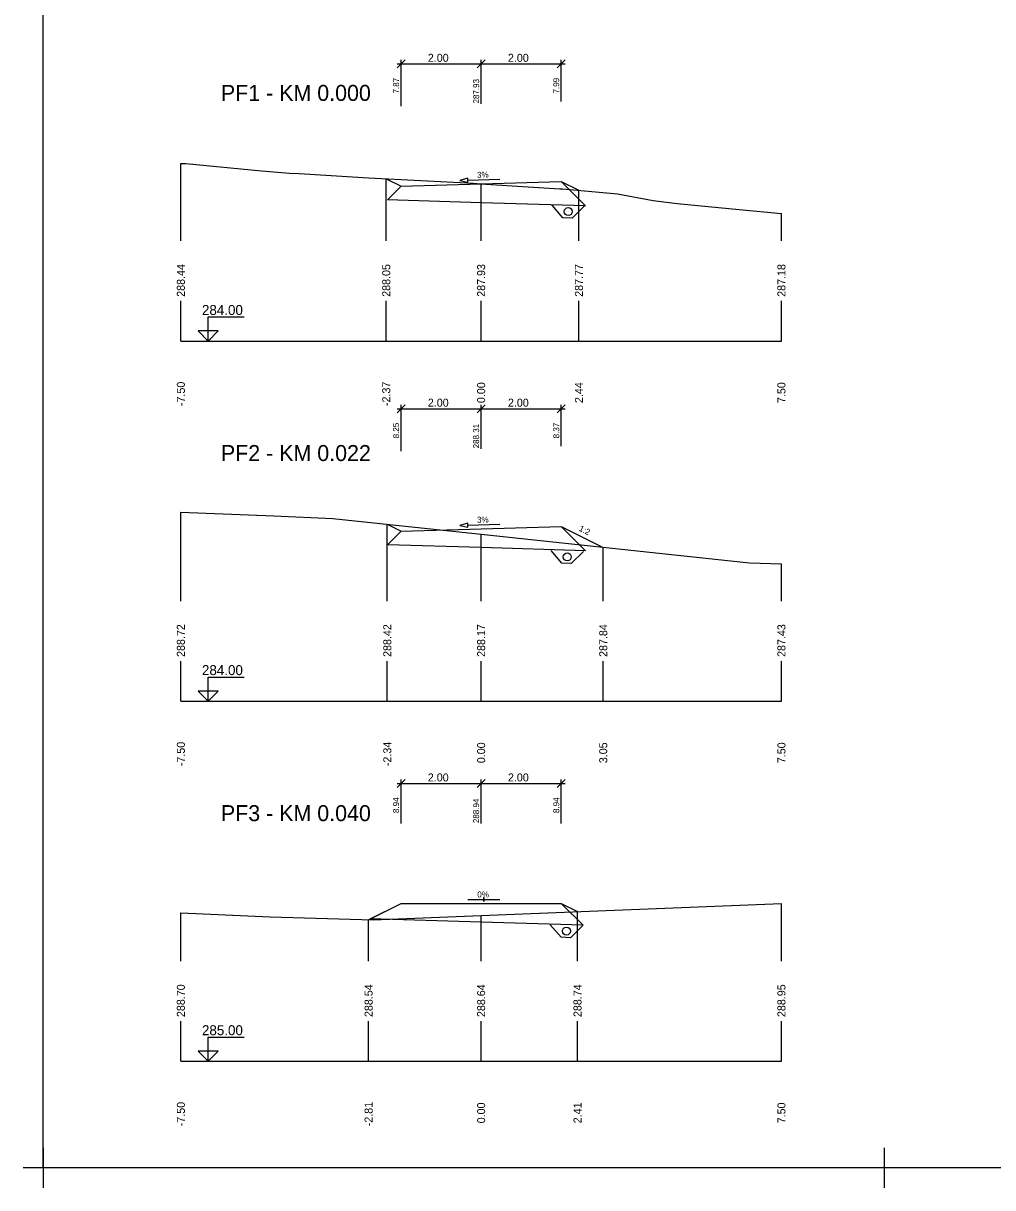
# Model space of a CAD drawing. Extents: x -9 to 2311, y -2 to 597.
# Drawn here: x -9.3 to 232.8, y -1.6 to 289.4 of the extents above; entities that cross this region are included whole.
import ezdxf

# ---------------------------------------------------------------- set-up
doc = ezdxf.new("R2010")
doc.units = 0
for name, color, linetype in [('KOTA', 7, 'Continuous'), ('KOTA_DELKY', 7, 'Continuous'), ('KOTA_DELKY_CONT', 7, 'Continuous'), ('NS_TELESO_VOZOVKY', 7, 'Continuous'), ('NS_V_PF', 7, 'Continuous'), ('REZY_PF_PUVODNI', 7, 'Continuous'), ('SESTAVY_REZU_PF', 7, 'Continuous'), ('SKLON', 7, 'Continuous'), ('SVK', 7, 'Continuous')]:
    doc.layers.add(name, color=color, linetype=linetype)

msp = doc.modelspace()

# ---------------------------------------------------------------- linework, layer by layer
for p, q in [((-4.35, 8.39), (-4.35, -1.61)), ((-4.35, 8.39), (-4.35, -1.61)), ((-4.35, 8.39), (-4.35, -1.61)), ((-4.35, 8.39), (-4.35, -1.61)), ((205.65, 8.39), (205.65, -1.61)), ((205.65, 8.39), (205.65, -1.61)), ((205.65, 8.39), (205.65, -1.61)), ((205.65, 8.39), (205.65, -1.61)), ((0.65, 3.39), (-9.35, 3.39)), ((0.65, 3.39), (-9.35, 3.39)), ((0.65, 3.39), (-9.35, 3.39)), ((0.65, 3.39), (-9.35, 3.39)), ((210.65, 3.39), (200.65, 3.39)), ((210.65, 3.39), (200.65, 3.39)), ((210.65, 3.39), (200.65, 3.39)), ((210.65, 3.39), (200.65, 3.39))]:
    msp.add_line(p, q)
msp.add_lwpolyline([(-4.35, 597.39), (2305.65, 597.39), (2305.65, 3.39), (-4.35, 3.39)], close=True)
for points in [[(130.8, 243.76), (127.75, 240.72), (125.4, 240.82), (122.7, 243.96)], [(130.58, 157.43), (127.52, 154.39), (125.18, 154.49), (122.47, 157.63)], [(130.38, 63.91), (127.33, 60.87), (124.98, 60.97), (122.27, 64.11)]]:
    msp.add_lwpolyline(points)
for centre in [(126.74, 242.36), (126.52, 156.03), (126.32, 62.51)]:
    msp.add_circle(centre, 1)
at = {"layer": 'KOTA'}
for points in [[(36.85, 212.5), (34.35, 212.5), (36.85, 210), (36.85, 216), (45.85, 216)], [(36.85, 210), (39.35, 212.5), (36.85, 212.5)], [(36.85, 122.5), (34.35, 122.5), (36.85, 120), (36.85, 126), (45.85, 126)], [(36.85, 120), (39.35, 122.5), (36.85, 122.5)], [(36.85, 32.5), (34.35, 32.5), (36.85, 30), (36.85, 36), (45.85, 36)], [(36.85, 30), (39.35, 32.5), (36.85, 32.5)]]:
    msp.add_lwpolyline(points, dxfattribs=at)
at = {"layer": 'KOTA_DELKY'}
for points in [[(84, 278.27), (86, 280.27)], [(85, 268.67), (85, 280.27)], [(104, 278.27), (106, 280.27)], [(104, 278.27), (106, 280.27)], [(105, 269.27), (105, 280.27)], [(105, 269.27), (105, 280.27)], [(124, 278.27), (126, 280.27)], [(125, 269.87), (125, 280.27)], [(84, 279.27), (106, 279.27)], [(104, 279.27), (126, 279.27)], [(84, 192.08), (86, 194.08)], [(84, 193.08), (106, 193.08)], [(85, 182.48), (85, 194.08)], [(104, 192.08), (106, 194.08)], [(104, 192.08), (106, 194.08)], [(104, 193.08), (126, 193.08)], [(105, 183.08), (105, 194.08)], [(105, 183.08), (105, 194.08)], [(124, 192.08), (126, 194.08)], [(125, 183.68), (125, 194.08)], [(84, 98.43), (86, 100.43)], [(84, 99.43), (106, 99.43)], [(85, 89.43), (85, 100.43)], [(104, 98.43), (106, 100.43)], [(104, 98.43), (106, 100.43)], [(104, 99.43), (126, 99.43)], [(105, 89.43), (105, 100.43)], [(105, 89.43), (105, 100.43)], [(124, 98.43), (126, 100.43)], [(125, 89.43), (125, 100.43)]]:
    msp.add_lwpolyline(points, dxfattribs=at)
at = {"layer": 'NS_TELESO_VOZOVKY'}
for points in [[(105, 249.27), (125, 249.87), (125, 249.87), (131.08, 243.79), (105, 244.57), (81.6, 245.28), (85, 248.67), (85, 248.67), (105, 249.27)], [(105, 163.08), (125, 163.68), (125, 163.68), (131.08, 157.6), (105, 158.38), (81.6, 159.08), (85, 162.48), (85, 162.48), (105, 163.08)], [(105, 69.43), (125, 69.43), (125, 69.43), (130.46, 63.97), (105, 64.73), (77.26, 65.57), (85, 69.43), (85, 69.43), (105, 69.43)]]:
    msp.add_lwpolyline(points, dxfattribs=at)
at = {"layer": 'NS_V_PF'}
for points in [[(81.3, 250.53), (85, 248.67), (85, 248.67), (105, 249.27), (125, 249.87), (125, 249.87), (129.43, 247.66)], [(81.56, 164.2), (85, 162.48), (85, 162.48), (105, 163.08), (125, 163.68), (125, 163.68), (135.5, 158.43)], [(76.89, 65.38), (85, 69.43), (85, 69.43), (105, 69.43), (125, 69.43), (125, 69.43), (129.07, 67.4)]]:
    msp.add_lwpolyline(points, dxfattribs=at)
at = {"layer": 'REZY_PF_PUVODNI'}
for points in [[(30, 254.39), (31.22, 254.33), (50.11, 252.52), (57.15, 251.92), (59.54, 251.82), (76.9, 250.75), (103, 249.42), (105, 249.27), (106.17, 249.19), (124.67, 248.02), (125.35, 248.04), (139.08, 246.77), (147.98, 245.13), (153.99, 244.34), (169.47, 242.89), (180, 241.85)], [(30, 167.2), (53.19, 166.28), (67.96, 165.65), (105, 161.69), (105, 161.69), (172.03, 154.52), (180, 154.35)], [(30, 67.05), (52.28, 66.11), (78, 65.34), (105, 66.43), (105, 66.43), (180, 69.45)]]:
    msp.add_lwpolyline(points, dxfattribs=at)
at = {"layer": 'SESTAVY_REZU_PF'}
for points in [[(30, 210), (180, 210)], [(30, 120), (180, 120)], [(30, 30), (180, 30)]]:
    msp.add_lwpolyline(points, dxfattribs=at)
at = {"layer": 'SKLON'}
for points in [[(101.64, 250.67), (99.66, 250.11), (101.67, 249.68), (101.64, 250.67)], [(101.65, 250.17), (109.65, 250.41)], [(101.64, 164.48), (99.66, 163.92), (101.67, 163.48), (101.64, 164.48)], [(101.65, 163.98), (109.65, 164.22)], [(101.68, 70.43), (109.68, 70.43)], [(105.68, 70.93), (105.68, 70.43), (105.68, 69.93), (105.68, 70.93)]]:
    msp.add_lwpolyline(points, dxfattribs=at)
at = {"layer": 'SVK'}
for points in [[(30, 235), (30, 254.39)], [(81.3, 235), (81.3, 250.53)], [(105, 235), (105, 249.27)], [(129.43, 235), (129.43, 247.66)], [(180, 235), (180, 241.85)], [(30, 210), (30, 220)], [(81.3, 210), (81.3, 220)], [(105, 210), (105, 220)], [(129.43, 210), (129.43, 220)], [(180, 210), (180, 220)], [(30, 145), (30, 167.2)], [(81.56, 145), (81.56, 164.2)], [(105, 145), (105, 161.69)], [(135.5, 145), (135.5, 158.43)], [(180, 145), (180, 154.35)], [(30, 120), (30, 130)], [(81.56, 120), (81.56, 130)], [(105, 120), (105, 130)], [(135.5, 120), (135.5, 130)], [(180, 120), (180, 130)], [(30, 55), (30, 67.05)], [(129.07, 55), (129.07, 67.4)], [(180, 55), (180, 69.45)], [(76.89, 55), (76.89, 65.38)], [(105, 55), (105, 66.43)], [(30, 30), (30, 40)], [(76.89, 30), (76.89, 40)], [(105, 30), (105, 40)], [(129.07, 30), (129.07, 40)], [(180, 30), (180, 40)]]:
    msp.add_lwpolyline(points, dxfattribs=at)

# ---------------------------------------------------------------- texts
at = {"layer": 'KOTA'}
for s, p in [('284.00', (35.27, 216.5)), ('284.00', (35.27, 126.5)), ('285.00', (35.27, 36.5))]:
    msp.add_text(s, height=2.5, dxfattribs=at).set_placement(p)
at = {"layer": 'KOTA_DELKY'}
for p in [(91.69, 279.77), (111.69, 279.77), (91.69, 193.58), (111.69, 193.58), (91.69, 99.93), (111.69, 99.93)]:
    msp.add_text('2.00', height=2, dxfattribs=at).set_placement(p)
at = {"layer": 'KOTA_DELKY_CONT'}
for s, p in [('7.87', (84.5, 271.86)), ('287.93', (104.5, 269.35)), ('7.99', (124.5, 271.86)), ('8.25', (84.5, 185.67)), ('288.31', (104.5, 183.16)), ('8.37', (124.5, 185.67)), ('8.94', (84.5, 92.02)), ('288.94', (104.5, 89.51)), ('8.94', (124.5, 92.02))]:
    msp.add_text(s, height=1.5, rotation=90, dxfattribs=at).set_placement(p)
at = {"layer": 'SESTAVY_REZU_PF'}
for s, p in [('PF1 - KM 0.000', (40, 270)), ('PF2 - KM 0.022', (40, 180)), ('PF3 - KM 0.040', (40, 90))]:
    msp.add_text(s, height=4, dxfattribs=at).set_placement(p)
at = {"layer": 'SKLON'}
for s, rotation, p in [('3%', 1.7184, (104, 250.75)), ('3%', 1.7184, (104, 164.55)), ('1:2', 333.4349, (129.29, 162.65))]:
    msp.add_text(s, height=1.5, rotation=rotation, dxfattribs=at).set_placement(p)
msp.add_text('0%', height=1.5, dxfattribs=at).set_placement((104.04, 70.93))
at = {"layer": 'SVK'}
for s, p in [(' 288.44', (31, 220.3)), (' 288.05', (82.3, 220.3)), (' 287.93', (106, 220.3)), (' 287.77', (130.43, 220.3)), (' 287.18', (181, 220.3)), (' -7.50', (31, 193)), (' -2.37', (82.3, 193)), ('  0.00', (106, 193)), ('  2.44', (130.43, 193)), ('  7.50', (181, 193)), (' 288.72', (31, 130.3)), (' 288.42', (82.56, 130.3)), (' 288.17', (106, 130.3)), (' 287.84', (136.5, 130.3)), (' 287.43', (181, 130.3)), (' -7.50', (31, 103)), (' -2.34', (82.56, 103)), ('  0.00', (106, 103)), ('  3.05', (136.5, 103)), ('  7.50', (181, 103)), (' 288.70', (31, 40.3)), (' 288.54', (77.89, 40.3)), (' 288.64', (106, 40.3)), (' 288.74', (130.07, 40.3)), (' 288.95', (181, 40.3)), (' -7.50', (31, 13)), (' -2.81', (77.89, 13)), ('  0.00', (106, 13)), ('  2.41', (130.07, 13)), ('  7.50', (181, 13))]:
    msp.add_text(s, height=2, rotation=90, dxfattribs=at).set_placement(p)

doc.saveas('drawing.dxf')
